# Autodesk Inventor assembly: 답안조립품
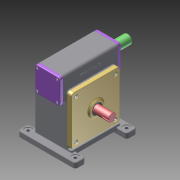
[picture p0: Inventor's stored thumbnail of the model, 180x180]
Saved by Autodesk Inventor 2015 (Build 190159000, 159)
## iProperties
Created: 2025-06
Part Number: 답안조립품
Document SubType Name: Assembly
Designer: User
Author: User
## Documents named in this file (13)
- C:\Users\User\Desktop\750603V1003\답안조립품.iam
- C:\Users\User\Desktop\750603V1003\가져온 구성요소\6각 구멍붙이 볼트 M8x20\6각 구멍붙이 볼트 M8x20.ipt
- C:\Users\User\Desktop\750603V1003\가져온 구성요소\깊은 홈 볼 베어링 6206\깊은 홈 볼 베어링 6206.ipt
- C:\Users\User\Desktop\750603V1003\가져온 구성요소\깊은 홈 볼 베어링 6209\깊은 홈 볼 베어링 6209.ipt
- C:\Users\User\Desktop\750603V1003\가져온 구성요소\뒷커버\뒷커버.ipt
- C:\Users\User\Desktop\750603V1003\본체.ipt
- C:\Users\User\Desktop\750603V1003\가져온 구성요소\앞커버\앞커버.ipt
- C:\Users\User\Desktop\750603V1003\가져온 구성요소\오일 실 30 42 7\오일 실 30 42 7.ipt
- C:\Users\User\Desktop\750603V1003\가져온 구성요소\오일 실 35 55 11\오일 실 35 55 11.ipt
- C:\Users\User\Desktop\750603V1003\가져온 구성요소\웜 샤프트\웜 샤프트.ipt
- C:\Users\User\Desktop\750603V1003\가져온 구성요소\웜 휠 커버\웜 휠 커버.ipt
- C:\Users\User\Desktop\750603V1003\가져온 구성요소\웜 휠\웜 휠.ipt
- C:\Users\User\Desktop\750603V1003\가져온 구성요소\6각 구멍붙이 볼트 M6x12\6각 구멍붙이 볼트 M6x12.ipt
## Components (12 placed, 2 different names)
1. 6각 구멍붙이 볼트 M6x12:1
2. 6각 구멍붙이 볼트 M6x12:2
3. 6각 구멍붙이 볼트 M6x12:3
4. 6각 구멍붙이 볼트 M6x12:4
5. 6각 구멍붙이 볼트 M6x12:5
6. 6각 구멍붙이 볼트 M6x12:6
7. 6각 구멍붙이 볼트 M6x12:7
8. 6각 구멍붙이 볼트 M6x12:8
9. 6각 구멍붙이 볼트 M8x20:1
10. 6각 구멍붙이 볼트 M8x20:2
11. 6각 구멍붙이 볼트 M8x20:3
12. 6각 구멍붙이 볼트 M8x20:4
